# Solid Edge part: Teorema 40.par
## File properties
Title: Teorema 40
Author: s.pallini
Template: Normal.par
Last saved by: s.pallini
Revision: 10
Application: Solid Edge
Tipo di contenuto documento: 0
Precisione: 0,990
Document Number: 8031-40
Revision: 0
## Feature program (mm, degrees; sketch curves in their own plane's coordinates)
sketch for "unnamed Protrusion 1" plane through (0, 0, 0) normal (0, 0, 1) x-axis (1, 0, 0)
  line (-190, -190) -> (190, -190)
  line (190, -190) -> (190, 190)
  line (190, 190) -> (-190, 190)
  line (-190, 190) -> (-190, -190)
  dimension (linear) = 190
  dimension (linear) = 190
extrude "unnamed Protrusion 1" add finite 130 along +normal
sketch for "ExtrudedCutout_1" plane through (0, 0, 0) normal (0, 0, -1) x-axis (1, 0, 0)
  line (-176, -176) -> (176, -176)
  line (176, -176) -> (176, 176)
  line (176, 176) -> (-176, 176)
  line (-176, 176) -> (-176, -176)
extrude "ExtrudedCutout_1" cut finite 80 along -normal  Treatment1_DraftAngle = 20 deg
sketch for "Foro_1" plane through (0, 0, 130) normal (0, 0, 1) x-axis (1, 0, 0)
  hole centre (0, 0) bore radius 25
hole "Foro_1" diameter 50 through
sketch for "ExtrudedCutout_2" #1 plane through (0, 0, 130) normal (0, 0, 1) x-axis (1, 0, 0)
  circle centre (0, 0) radius 35
sketch for "ExtrudedCutout_2" #2 plane through (0, 0, 130) normal (0, 0, 1) x-axis (1, 0, 0)
  line (-125, -145) -> (125, -145)
  arc centre (125, -125) radius 20 from (145, -125) to (125, -145) cw
  line (145, -125) -> (145, 125)
  arc centre (125, 125) radius 20 from (125, 145) to (145, 125) cw
  line (125, 145) -> (-125, 145)
  arc centre (-125, 125) radius 20 from (-145, 125) to (-125, 145) cw
  line (-145, 125) -> (-145, -125)
  arc centre (-125, -125) radius 20 from (-145, -125) to (-125, -145) ccw
  dimension (linear) = 125
  dimension (linear) = 145
extrude "ExtrudedCutout_2" cut finite 35 along -normal  Treatment1_DraftAngle = 10 deg
draft "Draft_1"  Angles1 = 10 deg
fillet "Rotondo_1" radius 8
fillet "Rotondo_3" radius 10
fillet "Rotondo_4" radius 5
fillet "Rotondo_6" radius 10
fillet "Rotondo_7" radius 10
fillet "Rotondo_8" radius 6
fillet "Rotondo_10" radius 6
fillet "Rotondo_11" radius 5
sketch for "Foro_2" plane through (0, 0, 130) normal (0, 0, 1) x-axis (1, 0, 0)
  hole centre (150, -160) bore radius 6
hole "Foro_2" diameter 12 finite
sketch for "unnamed Hole 1" plane through (0, 0, 130) normal (0, 0, 1) x-axis (1, 0, 0)
  hole centre (-150, -160) bore radius 6
  dimension (linear) = 150
hole "unnamed Hole 1" finite
sketch for "Foro_4" plane through (0, 0, 130) normal (0, 0, 1) x-axis (1, 0, 0)
  hole centre (-150, -160) bore radius 8
hole "Foro_4" diameter 16 finite
sketch for "unnamed Hole 2" plane through (0, 0, 130) normal (0, 0, 1) x-axis (1, 0, 0)
  hole centre (150, -160) bore radius 8
hole "unnamed Hole 2" finite
fillet "Rotondo_13" radius 6
pattern "unnamed Pattern 1" of "Foro_2", "unnamed Hole 1"
pattern "unnamed Pattern 2" of "Foro_4", "unnamed Hole 2"
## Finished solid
Body 1: solid body, 89 faces, 174 edges, 88 vertices.
  Faces by surface: cylinder 37, plane 21, torus 14, sphere 8, cone 5, blend 4
  Edges by curve: circle 94, line 72, ellipse 8
Bounding box of the edges (mm; curved faces can reach further): 380.000 x 380.000 x 130.000, from (-190, -190, 0) to (190, 190, 130).
Cylindrical faces by radius (mm): R5 x4, R6 x14, R8 x6, R10 x12, R25 x1
Conical faces (half-angle, radius in mm at the cone's reference point): 10 deg R20 x4, 10 deg R35 x1
Toroidal faces (ring radius, tube radius in mm): R1 r5 x4, R5.4376 r10 x4, R26.7128 r8 x4, R35 r10 x1, R49.5624 r10 x1
Spherical faces by radius (mm): R6 x4, R10 x4
Planar faces by outward normal: +x 1, +y 1, +z 7, -x 1, -y 1, -z 2, oblique 8
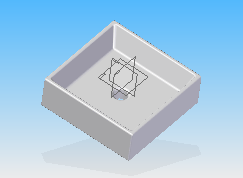
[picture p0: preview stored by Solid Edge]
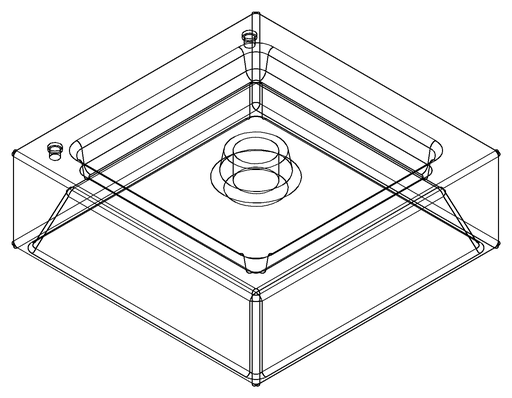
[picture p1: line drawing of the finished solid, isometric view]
